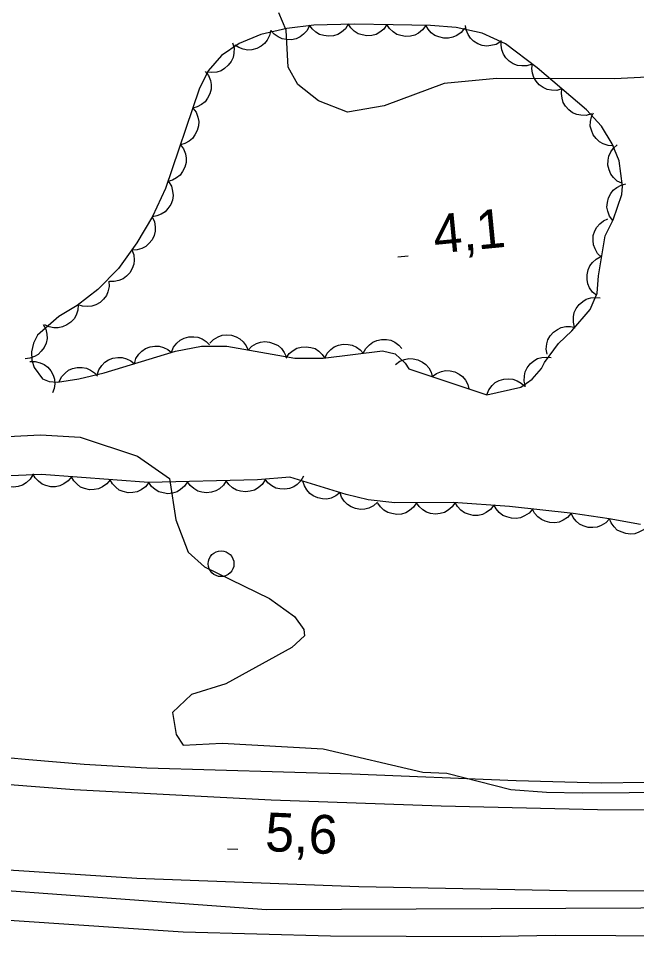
# Model space of a CAD drawing. Extents: x 336540 to 340074, y 5572036 to 5573747.
# Drawn here: x 337091.5 to 337139.3, y 5572550.4 to 5572621.6 of the extents above; entities that cross this region are included whole.
import ezdxf

# ---------------------------------------------------------------- set-up
doc = ezdxf.new("R2010")
doc.units = 0
for name, color, linetype in [('Niveau 1', 7, 'Continuous'), ('Niveau 2', 7, 'Continuous'), ('Niveau 21', 7, 'Continuous'), ('Niveau 3', 7, 'Continuous'), ('Niveau 36', 7, 'Continuous'), ('Niveau 44', 7, 'Continuous')]:
    doc.layers.add(name, color=color, linetype=linetype)

msp = doc.modelspace()

# ---------------------------------------------------------------- linework, layer by layer
at = {"layer": 'Niveau 1'}
for points in [[(337087.6, 5572589.07), (337093.18, 5572589.35), (337096.24, 5572589.17), (337100.7, 5572587.68), (337103.16, 5572585.95), (337103.66, 5572582.76), (337104.62, 5572580.26), (337105.88, 5572579.12), (337110.91, 5572576.68), (337112.85, 5572575.27), (337113.57, 5572574.28), (337113.61, 5572573.78), (337112.63, 5572572.87), (337107.53, 5572570.07), (337104.86, 5572569.24), (337103.4, 5572567.83), (337103.68, 5572566.13), (337104.22, 5572565.31), (337107.25, 5572565.48), (337115.05, 5572565.03), (337122.78, 5572563.22), (337124.64, 5572563.15), (337129.59, 5572561.88), (337132.35, 5572561.68), (337135.12, 5572561.61), (337145.99, 5572561.71)], [(337177.11, 5572554.26), (337177.36, 5572553.6), (337177.42, 5572552.66), (337177.14, 5572551.79), (337176.27, 5572551.45), (337169.72, 5572551.22), (337163.71, 5572550.82), (337149.49, 5572550.41), (337147.1, 5572550.49), (337133.01, 5572550.58), (337127.35, 5572550.47), (337115.64, 5572550.52), (337104.22, 5572550.84), (337087.28, 5572551.97)]]:
    msp.add_lwpolyline(points, dxfattribs=at)
at = {"layer": 'Niveau 2'}
msp.add_lwpolyline([(337181.57, 5572617.63), (337176.35, 5572617.01), (337168.16, 5572618.29), (337164.37, 5572619.46), (337156.03, 5572620.71), (337151.47, 5572620.32), (337143.67, 5572617.21), (337137.62, 5572616.9), (337128.47, 5572616.93), (337124.42, 5572616.56), (337119.78, 5572614.81), (337116.94, 5572614.32), (337114.69, 5572615.22), (337113.09, 5572616.48), (337112.34, 5572617.81), (337112.2, 5572620.69), (337111.63, 5572622.02)], dxfattribs=at)
at = {"layer": 'Niveau 21'}
for points in [[(337067.1, 5572566.52), (337092.27, 5572564.2), (337096.55, 5572563.84), (337101.41, 5572563.55), (337117.29, 5572563.1), (337129.99, 5572562.58), (337136.6, 5572562.4), (337153.26, 5572562.66), (337170.49, 5572562.67), (337177.39, 5572562.83), (337181.83, 5572563.02), (337202.37, 5572564.24), (337213.14, 5572564.75), (337219.59, 5572565.17), (337255.85, 5572568.43), (337280.4, 5572570.85), (337289.47, 5572571.86), (337370.68, 5572582.43), (337393.64, 5572585.48), (337410.56, 5572587.83), (337420.85, 5572589.04), (337469.47, 5572594.26)], [(337475.89, 5572592.36), (337426.83, 5572587.03), (337409.93, 5572585.09), (337387.78, 5572582.21), (337292.3, 5572570.26), (337250.14, 5572565.61), (337233.14, 5572564.02), (337216.87, 5572562.87), (337197.38, 5572561.67), (337181.62, 5572560.93), (337173.83, 5572560.67), (337157.89, 5572560.36), (337143.02, 5572560.27), (337136.29, 5572560.31), (337124.2, 5572560.58), (337111.04, 5572561.06), (337095.79, 5572561.86), (337085.79, 5572562.64)], [(337073.99, 5572555.28), (337110.67, 5572552.6), (337151.23, 5572552.78), (337188.2, 5572553.24), (337232.65, 5572555.84), (337279.67, 5572560.35), (337323.44, 5572565.76), (337344.89, 5572568.84), (337348.4, 5572569.26), (337352.81, 5572569.65), (337362.62, 5572571.35), (337367.63, 5572572.04), (337373.89, 5572572.71), (337392.31, 5572574.42), (337443.52, 5572580.72), (337457.51, 5572582.4)], [(337352.94, 5572571.52), (337305.72, 5572565.51), (337279.5, 5572562.41), (337244.11, 5572558.62), (337235.32, 5572557.79), (337223.99, 5572556.9), (337216.56, 5572556.58), (337194.91, 5572555.24), (337184.99, 5572554.79), (337169.91, 5572554.32), (337150.52, 5572554.01), (337133.92, 5572554.03), (337117.83, 5572554.35), (337100.64, 5572555), (337088.68, 5572555.77)]]:
    msp.add_lwpolyline(points, dxfattribs=at)
at = {"layer": 'Niveau 3'}
for p, q in [((337120.85, 5572603.13), (337121.65, 5572603.21)), ((337107.65, 5572557.29), (337108.45, 5572557.25))]:
    msp.add_line(p, q, dxfattribs=at)
at = {"layer": 'Niveau 36'}
msp.add_circle((337107.159, 5572579.361), 1, dxfattribs=at)
at = {"layer": 'Niveau 44'}
for points in [[(337127.73, 5572592.45), (337130.36, 5572593.03), (337131.23, 5572593.66), (337131.96, 5572594.47), (337132.19, 5572594.94), (337133.27, 5572596.42), (337134.3, 5572597.41), (337135.73, 5572599.06), (337136.26, 5572600.31), (337136.38, 5572601.66), (337136.88, 5572604.75), (337137.5, 5572606), (337138.19, 5572607.95), (337138.22, 5572608.6), (337137.97, 5572610.55), (337137.44, 5572611.88), (337136.62, 5572613.24), (337135.45, 5572614.51), (337131.63, 5572617.76), (337129.18, 5572619.62), (337127.36, 5572620.46), (337125.35, 5572620.89), (337123.37, 5572621.04), (337120.48, 5572621.1), (337117.46, 5572621.15), (337114.35, 5572621.08), (337112.24, 5572620.8), (337110.23, 5572620.35), (337108.55, 5572619.66), (337107.19, 5572618.71), (337106.17, 5572617.53), (337105.47, 5572616.12), (337102.85, 5572608.41), (337101.85, 5572606.26), (337100.63, 5572604.2), (337099.23, 5572602.23), (337097.63, 5572600.6), (337096.02, 5572599.36), (337094.59, 5572598.51), (337092.95, 5572597.05), (337092.63, 5572596.44), (337092.48, 5572595.78), (337092.51, 5572595.13), (337092.68, 5572594.56), (337093.33, 5572593.67), (337093.84, 5572593.48), (337094.49, 5572593.43), (337096.14, 5572593.67), (337098.11, 5572594.14), (337103.62, 5572595.81), (337105.65, 5572596.2), (337107.61, 5572596.2), (337112.87, 5572595.28), (337115.05, 5572595.27), (337119.66, 5572595.84), (337120.64, 5572595.61), (337121.41, 5572594.89), (337121.69, 5572594.45), (337127.73, 5572592.45)], [(337111.01, 5572620.67), (337110.92, 5572620.26), (337110.73, 5572619.9), (337110.53, 5572619.64), (337110.25, 5572619.43), (337109.93, 5572619.26), (337109.55, 5572619.17), (337109.23, 5572619.13), (337108.88, 5572619.2), (337108.53, 5572619.33), (337108.23, 5572619.53)], [(337114.01, 5572621.03), (337113.82, 5572620.66), (337113.54, 5572620.37), (337113.28, 5572620.16), (337112.96, 5572620.02), (337112.6, 5572619.94), (337112.22, 5572619.96), (337111.89, 5572620), (337111.58, 5572620.16), (337111.27, 5572620.37), (337111.03, 5572620.64)], [(337117, 5572621.14), (337116.78, 5572620.79), (337116.47, 5572620.53), (337116.19, 5572620.35), (337115.85, 5572620.25), (337115.48, 5572620.21), (337115.11, 5572620.26), (337114.79, 5572620.35), (337114.49, 5572620.53), (337114.21, 5572620.78), (337114, 5572621.07)], [(337120, 5572621.11), (337119.76, 5572620.77), (337119.44, 5572620.52), (337119.16, 5572620.35), (337118.82, 5572620.26), (337118.45, 5572620.24), (337118.07, 5572620.31), (337117.76, 5572620.4), (337117.47, 5572620.6), (337117.2, 5572620.86), (337117, 5572621.16)], [(337123, 5572621.05), (337122.76, 5572620.71), (337122.44, 5572620.46), (337122.15, 5572620.29), (337121.81, 5572620.21), (337121.44, 5572620.18), (337121.07, 5572620.26), (337120.76, 5572620.35), (337120.47, 5572620.55), (337120.2, 5572620.81), (337120, 5572621.11)], [(337126, 5572620.84), (337125.74, 5572620.51), (337125.4, 5572620.28), (337125.11, 5572620.13), (337124.76, 5572620.07), (337124.39, 5572620.06), (337124.02, 5572620.16), (337123.71, 5572620.27), (337123.43, 5572620.48), (337123.18, 5572620.76), (337123, 5572621.07)], [(337128.81, 5572619.79), (337128.45, 5572619.58), (337128.05, 5572619.48), (337127.73, 5572619.44), (337127.38, 5572619.5), (337127.03, 5572619.62), (337126.71, 5572619.84), (337126.47, 5572620.05), (337126.28, 5572620.35), (337126.14, 5572620.7), (337126.08, 5572621.05)], [(337131.24, 5572618.06), (337130.84, 5572617.92), (337130.44, 5572617.91), (337130.11, 5572617.94), (337129.78, 5572618.08), (337129.47, 5572618.27), (337129.21, 5572618.55), (337129.01, 5572618.81), (337128.9, 5572619.15), (337128.83, 5572619.51), (337128.85, 5572619.87)], [(337108.05, 5572619.71), (337108.16, 5572619.3), (337108.15, 5572618.9), (337108.09, 5572618.57), (337107.94, 5572618.26), (337107.72, 5572617.96), (337107.43, 5572617.71), (337107.16, 5572617.53), (337106.82, 5572617.44), (337106.45, 5572617.4), (337106.09, 5572617.44)], [(337133.54, 5572616.13), (337133.14, 5572616.02), (337132.73, 5572616.03), (337132.41, 5572616.08), (337132.09, 5572616.23), (337131.79, 5572616.45), (337131.54, 5572616.74), (337131.36, 5572617.01), (337131.26, 5572617.35), (337131.22, 5572617.72), (337131.26, 5572618.08)], [(337105.94, 5572617.49), (337106.19, 5572617.16), (337106.33, 5572616.78), (337106.4, 5572616.46), (337106.38, 5572616.11), (337106.29, 5572615.75), (337106.11, 5572615.41), (337105.92, 5572615.14), (337105.65, 5572614.93), (337105.32, 5572614.75), (337104.97, 5572614.65)], [(337135.83, 5572614.19), (337135.42, 5572614.08), (337135.02, 5572614.09), (337134.69, 5572614.14), (337134.37, 5572614.29), (337134.07, 5572614.5), (337133.83, 5572614.8), (337133.65, 5572615.07), (337133.55, 5572615.41), (337133.5, 5572615.78), (337133.54, 5572616.13)], [(337104.97, 5572614.65), (337105.22, 5572614.32), (337105.36, 5572613.94), (337105.44, 5572613.62), (337105.41, 5572613.27), (337105.32, 5572612.91), (337105.14, 5572612.57), (337104.96, 5572612.3), (337104.68, 5572612.09), (337104.35, 5572611.91), (337104.01, 5572611.81)], [(337137.53, 5572611.73), (337137.12, 5572611.75), (337136.73, 5572611.89), (337136.44, 5572612.04), (337136.19, 5572612.28), (337135.97, 5572612.58), (337135.83, 5572612.94), (337135.74, 5572613.25), (337135.76, 5572613.6), (337135.83, 5572613.97), (337135.98, 5572614.29)], [(337104.01, 5572611.81), (337104.26, 5572611.48), (337104.4, 5572611.1), (337104.47, 5572610.78), (337104.45, 5572610.43), (337104.36, 5572610.07), (337104.18, 5572609.73), (337103.99, 5572609.46), (337103.71, 5572609.25), (337103.39, 5572609.07), (337103.04, 5572608.97)], [(337138.19, 5572608.82), (337137.82, 5572609), (337137.53, 5572609.28), (337137.32, 5572609.54), (337137.19, 5572609.87), (337137.11, 5572610.23), (337137.12, 5572610.61), (337137.17, 5572610.93), (337137.33, 5572611.25), (337137.54, 5572611.55), (337137.81, 5572611.79)], [(337103.1, 5572608.95), (337103.32, 5572608.59), (337103.41, 5572608.2), (337103.45, 5572607.87), (337103.39, 5572607.52), (337103.26, 5572607.18), (337103.05, 5572606.86), (337102.83, 5572606.61), (337102.53, 5572606.43), (337102.19, 5572606.29), (337101.84, 5572606.23)], [(337137.48, 5572605.94), (337137.23, 5572606.28), (337137.09, 5572606.66), (337137.03, 5572606.98), (337137.06, 5572607.33), (337137.15, 5572607.69), (337137.33, 5572608.03), (337137.52, 5572608.29), (337137.8, 5572608.5), (337138.13, 5572608.68), (337138.48, 5572608.77)], [(337101.83, 5572606.23), (337102.01, 5572605.85), (337102.07, 5572605.45), (337102.07, 5572605.12), (337101.98, 5572604.78), (337101.82, 5572604.45), (337101.57, 5572604.16), (337101.34, 5572603.93), (337101.02, 5572603.78), (337100.66, 5572603.67), (337100.3, 5572603.65)], [(337136.61, 5572603.1), (337136.31, 5572603.39), (337136.11, 5572603.74), (337135.98, 5572604.05), (337135.95, 5572604.4), (337135.97, 5572604.77), (337136.1, 5572605.13), (337136.24, 5572605.43), (337136.47, 5572605.68), (337136.77, 5572605.91), (337137.09, 5572606.06)], [(337100.26, 5572603.68), (337100.41, 5572603.29), (337100.43, 5572602.88), (337100.41, 5572602.55), (337100.28, 5572602.22), (337100.1, 5572601.9), (337099.83, 5572601.63), (337099.57, 5572601.43), (337099.24, 5572601.3), (337098.88, 5572601.23), (337098.52, 5572601.23)], [(337136.24, 5572600.13), (337135.92, 5572600.39), (337135.69, 5572600.73), (337135.55, 5572601.03), (337135.49, 5572601.37), (337135.49, 5572601.74), (337135.58, 5572602.11), (337135.7, 5572602.42), (337135.92, 5572602.69), (337136.19, 5572602.94), (337136.51, 5572603.12)], [(337098.47, 5572601.25), (337098.5, 5572600.83), (337098.4, 5572600.43), (337098.28, 5572600.13), (337098.07, 5572599.85), (337097.8, 5572599.6), (337097.46, 5572599.42), (337097.16, 5572599.3), (337096.8, 5572599.27), (337096.44, 5572599.3), (337096.09, 5572599.42)], [(337134.53, 5572597.68), (337134.43, 5572598.08), (337134.44, 5572598.49), (337134.49, 5572598.82), (337134.65, 5572599.13), (337134.87, 5572599.43), (337135.16, 5572599.67), (337135.43, 5572599.85), (337135.77, 5572599.95), (337136.14, 5572599.99), (337136.5, 5572599.95)], [(337096.1, 5572599.41), (337096.08, 5572598.99), (337095.93, 5572598.61), (337095.78, 5572598.32), (337095.53, 5572598.07), (337095.23, 5572597.85), (337094.88, 5572597.71), (337094.56, 5572597.63), (337094.21, 5572597.64), (337093.85, 5572597.72), (337093.52, 5572597.87)], [(337093.39, 5572597.89), (337093.59, 5572597.53), (337093.67, 5572597.13), (337093.69, 5572596.8), (337093.61, 5572596.45), (337093.47, 5572596.11), (337093.24, 5572595.81), (337093.01, 5572595.57), (337092.71, 5572595.4), (337092.36, 5572595.28), (337092, 5572595.24)], [(337106.29, 5572596.43), (337106.58, 5572596.73), (337106.94, 5572596.93), (337107.24, 5572597.05), (337107.59, 5572597.08), (337107.96, 5572597.05), (337108.32, 5572596.92), (337108.62, 5572596.78), (337108.87, 5572596.54), (337109.1, 5572596.24), (337109.25, 5572595.91)], [(337132.4, 5572595.58), (337132.32, 5572595.99), (337132.37, 5572596.39), (337132.46, 5572596.71), (337132.64, 5572597.01), (337132.88, 5572597.29), (337133.2, 5572597.51), (337133.49, 5572597.66), (337133.84, 5572597.73), (337134.21, 5572597.73), (337134.56, 5572597.66)], [(337103.31, 5572595.75), (337103.48, 5572596.14), (337103.74, 5572596.45), (337103.98, 5572596.67), (337104.3, 5572596.82), (337104.66, 5572596.92), (337105.04, 5572596.93), (337105.37, 5572596.9), (337105.69, 5572596.77), (337106.01, 5572596.57), (337106.26, 5572596.32)], [(337109.25, 5572595.91), (337109.54, 5572596.21), (337109.89, 5572596.41), (337110.2, 5572596.53), (337110.55, 5572596.56), (337110.92, 5572596.53), (337111.28, 5572596.4), (337111.57, 5572596.26), (337111.83, 5572596.02), (337112.05, 5572595.73), (337112.2, 5572595.4)], [(337115.19, 5572595.29), (337115.38, 5572595.66), (337115.66, 5572595.95), (337115.92, 5572596.16), (337116.25, 5572596.29), (337116.61, 5572596.37), (337116.99, 5572596.35), (337117.31, 5572596.3), (337117.63, 5572596.14), (337117.93, 5572595.93), (337118.17, 5572595.66)], [(337118.17, 5572595.66), (337118.36, 5572596.03), (337118.64, 5572596.32), (337118.9, 5572596.53), (337119.22, 5572596.66), (337119.59, 5572596.73), (337119.97, 5572596.72), (337120.29, 5572596.67), (337120.61, 5572596.51), (337120.91, 5572596.29), (337121.14, 5572596.02)], [(337100.45, 5572594.85), (337100.57, 5572595.25), (337100.8, 5572595.58), (337101.02, 5572595.83), (337101.32, 5572596.02), (337101.66, 5572596.15), (337102.04, 5572596.2), (337102.37, 5572596.21), (337102.71, 5572596.11), (337103.04, 5572595.95), (337103.32, 5572595.72)], [(337112.19, 5572595.28), (337112.43, 5572595.63), (337112.74, 5572595.88), (337113.03, 5572596.05), (337113.37, 5572596.14), (337113.74, 5572596.17), (337114.11, 5572596.11), (337114.43, 5572596.02), (337114.72, 5572595.82), (337114.99, 5572595.57), (337115.19, 5572595.27)], [(337092.35, 5572595.02), (337092.77, 5572595.03), (337093.16, 5572594.93), (337093.46, 5572594.8), (337093.74, 5572594.58), (337093.98, 5572594.3), (337094.15, 5572593.96), (337094.26, 5572593.65), (337094.28, 5572593.3), (337094.24, 5572592.93), (337094.12, 5572592.59)], [(337097.58, 5572593.98), (337097.7, 5572594.38), (337097.93, 5572594.71), (337098.15, 5572594.96), (337098.45, 5572595.15), (337098.79, 5572595.28), (337099.17, 5572595.33), (337099.5, 5572595.34), (337099.84, 5572595.24), (337100.17, 5572595.08), (337100.45, 5572594.85)], [(337120.66, 5572594.79), (337120.99, 5572595.05), (337121.37, 5572595.19), (337121.69, 5572595.26), (337122.04, 5572595.24), (337122.4, 5572595.16), (337122.74, 5572594.98), (337123.01, 5572594.8), (337123.23, 5572594.52), (337123.41, 5572594.19), (337123.51, 5572593.85)], [(337130.72, 5572593.09), (337130.62, 5572593.5), (337130.64, 5572593.9), (337130.7, 5572594.23), (337130.86, 5572594.54), (337131.08, 5572594.83), (337131.38, 5572595.07), (337131.66, 5572595.25), (337132, 5572595.33), (337132.37, 5572595.37), (337132.72, 5572595.32)], [(337094.63, 5572593.45), (337094.81, 5572593.83), (337095.08, 5572594.12), (337095.34, 5572594.34), (337095.66, 5572594.47), (337096.02, 5572594.56), (337096.4, 5572594.55), (337096.73, 5572594.51), (337097.05, 5572594.36), (337097.35, 5572594.15), (337097.6, 5572593.88)], [(337123.51, 5572593.85), (337123.84, 5572594.1), (337124.22, 5572594.25), (337124.54, 5572594.32), (337124.89, 5572594.3), (337125.25, 5572594.22), (337125.59, 5572594.04), (337125.86, 5572593.85), (337126.08, 5572593.58), (337126.26, 5572593.25), (337126.35, 5572592.91)], [(337127.73, 5572592.45), (337127.88, 5572592.84), (337128.14, 5572593.16), (337128.38, 5572593.39), (337128.69, 5572593.55), (337129.04, 5572593.66), (337129.42, 5572593.68), (337129.75, 5572593.66), (337130.08, 5572593.53), (337130.4, 5572593.34), (337130.66, 5572593.1)], [(337139.63, 5572582.39), (337137.21, 5572582.85), (337134.42, 5572583.25), (337129.48, 5572583.8), (337125.12, 5572584.11), (337120.61, 5572584.07), (337118.54, 5572584.31), (337116.83, 5572584.73), (337112.48, 5572586.06), (337109.99, 5572585.85), (337101.55, 5572585.64), (337093.25, 5572586.28), (337088.45, 5572586.07)], [(337092.59, 5572586.25), (337092.37, 5572585.9), (337092.07, 5572585.63), (337091.79, 5572585.44), (337091.46, 5572585.34), (337091.09, 5572585.29), (337090.71, 5572585.34), (337090.39, 5572585.41), (337090.09, 5572585.59), (337089.81, 5572585.83), (337089.59, 5572586.12)], [(337095.58, 5572586.1), (337095.32, 5572585.77), (337094.99, 5572585.54), (337094.69, 5572585.39), (337094.35, 5572585.33), (337093.98, 5572585.33), (337093.6, 5572585.42), (337093.3, 5572585.53), (337093.02, 5572585.75), (337092.77, 5572586.02), (337092.59, 5572586.33)], [(337098.57, 5572585.87), (337098.31, 5572585.54), (337097.98, 5572585.31), (337097.68, 5572585.16), (337097.34, 5572585.1), (337096.97, 5572585.09), (337096.6, 5572585.19), (337096.29, 5572585.3), (337096.01, 5572585.52), (337095.76, 5572585.79), (337095.58, 5572586.1)], [(337101.56, 5572585.64), (337101.3, 5572585.31), (337100.97, 5572585.08), (337100.67, 5572584.93), (337100.33, 5572584.87), (337099.96, 5572584.86), (337099.59, 5572584.96), (337099.28, 5572585.07), (337099, 5572585.28), (337098.75, 5572585.56), (337098.57, 5572585.87)], [(337104.56, 5572585.71), (337104.34, 5572585.36), (337104.03, 5572585.1), (337103.75, 5572584.92), (337103.41, 5572584.82), (337103.04, 5572584.78), (337102.67, 5572584.84), (337102.35, 5572584.92), (337102.05, 5572585.1), (337101.77, 5572585.35), (337101.56, 5572585.64)], [(337107.56, 5572585.79), (337107.34, 5572585.44), (337107.03, 5572585.17), (337106.75, 5572585), (337106.41, 5572584.9), (337106.04, 5572584.86), (337105.66, 5572584.91), (337105.35, 5572584.99), (337105.05, 5572585.18), (337104.77, 5572585.42), (337104.56, 5572585.71)], [(337110.56, 5572585.86), (337110.34, 5572585.51), (337110.03, 5572585.25), (337109.75, 5572585.07), (337109.41, 5572584.97), (337109.04, 5572584.93), (337108.66, 5572584.98), (337108.35, 5572585.06), (337108.05, 5572585.25), (337107.77, 5572585.5), (337107.56, 5572585.79)], [(337113.55, 5572586.15), (337113.34, 5572585.79), (337113.05, 5572585.5), (337112.78, 5572585.31), (337112.45, 5572585.19), (337112.09, 5572585.13), (337111.71, 5572585.16), (337111.39, 5572585.22), (337111.08, 5572585.39), (337110.78, 5572585.62), (337110.56, 5572585.9)], [(337116.37, 5572584.87), (337116.05, 5572584.61), (337115.67, 5572584.45), (337115.35, 5572584.37), (337115, 5572584.39), (337114.64, 5572584.46), (337114.3, 5572584.63), (337114.02, 5572584.81), (337113.8, 5572585.08), (337113.61, 5572585.4), (337113.5, 5572585.75)], [(337119.28, 5572584.13), (337118.97, 5572583.85), (337118.6, 5572583.67), (337118.29, 5572583.58), (337117.94, 5572583.57), (337117.57, 5572583.63), (337117.22, 5572583.78), (337116.94, 5572583.94), (337116.7, 5572584.2), (337116.49, 5572584.51), (337116.37, 5572584.84)], [(337122.29, 5572584.08), (337122.06, 5572583.74), (337121.74, 5572583.48), (337121.46, 5572583.3), (337121.12, 5572583.21), (337120.76, 5572583.18), (337120.38, 5572583.24), (337120.06, 5572583.32), (337119.77, 5572583.51), (337119.49, 5572583.76), (337119.29, 5572584.06)], [(337125.29, 5572584.11), (337125.06, 5572583.76), (337124.74, 5572583.5), (337124.46, 5572583.33), (337124.12, 5572583.24), (337123.76, 5572583.2), (337123.38, 5572583.26), (337123.06, 5572583.35), (337122.77, 5572583.54), (337122.49, 5572583.79), (337122.29, 5572584.08)], [(337128.28, 5572583.89), (337128.02, 5572583.56), (337127.69, 5572583.32), (337127.4, 5572583.17), (337127.05, 5572583.11), (337126.68, 5572583.1), (337126.31, 5572583.19), (337126, 5572583.3), (337125.72, 5572583.52), (337125.47, 5572583.79), (337125.29, 5572584.1)], [(337131.27, 5572583.6), (337131, 5572583.28), (337130.65, 5572583.06), (337130.35, 5572582.92), (337130.01, 5572582.87), (337129.64, 5572582.88), (337129.27, 5572582.99), (337128.97, 5572583.11), (337128.69, 5572583.33), (337128.45, 5572583.61), (337128.28, 5572583.93)], [(337134.25, 5572583.27), (337133.98, 5572582.95), (337133.63, 5572582.73), (337133.34, 5572582.59), (337132.99, 5572582.54), (337132.62, 5572582.55), (337132.25, 5572582.65), (337131.95, 5572582.78), (337131.68, 5572583), (337131.43, 5572583.28), (337131.27, 5572583.6)], [(337137.22, 5572582.85), (337136.94, 5572582.54), (337136.59, 5572582.33), (337136.28, 5572582.2), (337135.94, 5572582.16), (337135.57, 5572582.18), (337135.2, 5572582.3), (337134.9, 5572582.43), (337134.64, 5572582.66), (337134.41, 5572582.95), (337134.25, 5572583.27)], [(337140.17, 5572582.29), (337139.87, 5572581.99), (337139.51, 5572581.8), (337139.2, 5572581.68), (337138.85, 5572581.66), (337138.48, 5572581.7), (337138.13, 5572581.83), (337137.83, 5572581.97), (337137.58, 5572582.22), (337137.36, 5572582.52), (337137.22, 5572582.85)]]:
    msp.add_lwpolyline(points, dxfattribs=at)

# ---------------------------------------------------------------- texts
at = {"layer": 'Niveau 3'}
for s, rotation, p in [('4,1    ', 5.5424, (337123.72, 5572603.37)), ('5,6    ', 357.34228, (337110.53, 5572557.12))]:
    msp.add_text(s, height=3, rotation=rotation, dxfattribs=at).set_placement(p)

doc.saveas('drawing.dxf')
